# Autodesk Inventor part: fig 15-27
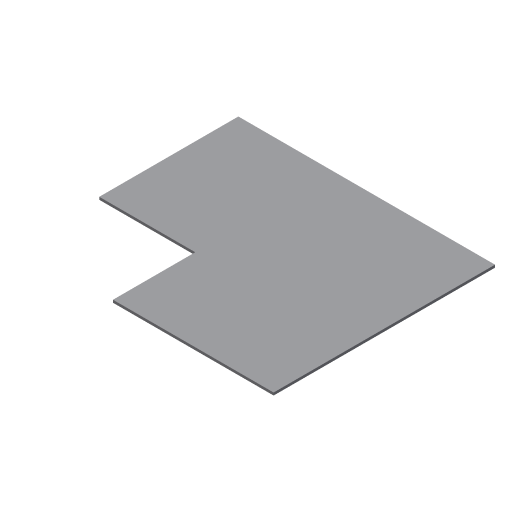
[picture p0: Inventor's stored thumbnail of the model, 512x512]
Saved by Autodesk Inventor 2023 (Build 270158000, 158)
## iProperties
Created: 2005-03
Part Number: fig 15-27
Document SubType Name: Sheet Metal
Designer: CADCIM
Manufacturer: Standard
Standards Organization: Custom
Density: 1 g/cm^3
Sheet Metal Rule: Default
Material: Generic
Appearance: Default
Author: CADCIM
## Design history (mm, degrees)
node "Face1"
  sketch "Sketch1"
    geometry: L1 (29.25, 32.25)-(-19.875, 32.25); L2 (-19.875, 32.25)-(-19.875, 5.625); L3 (-19.875, 5.625)-(-1.5, 5.625); L4 (-1.5, 5.625)-(-1.5, -10.125); L5 (-1.5, -10.125)-(29.25, -10.125); L6 (29.25, -10.125)-(29.25, 32.25)
    constraints: 12 end point, 4 parallel, 1 horizontal, 1 perpendicular
body "Solid1"
face "Plate1" dims "d1" = 0.5 (= Thickness)
other parameters: "Thickness" = 0.5, "BendRadius" = 0.5 (= Thickness), "BendReliefWidth" = 0.5 (= Thickness), "BendReliefDepth" = 0.25 (= 0.5 x Thickness), "CornerReliefSize" = 2 (= 4 x Thickness), "SeamGap" = 0.01, "MinimumRemnant" = 1 (= 2 x Thickness), "TransitionRadius" = 0.5 (= BendRadius), "JacobiRadiusSize" = 0.5 (= Thickness), "GapSize" = 0.5 (= Thickness), "d0" = 0.5 (= BendRadius)
